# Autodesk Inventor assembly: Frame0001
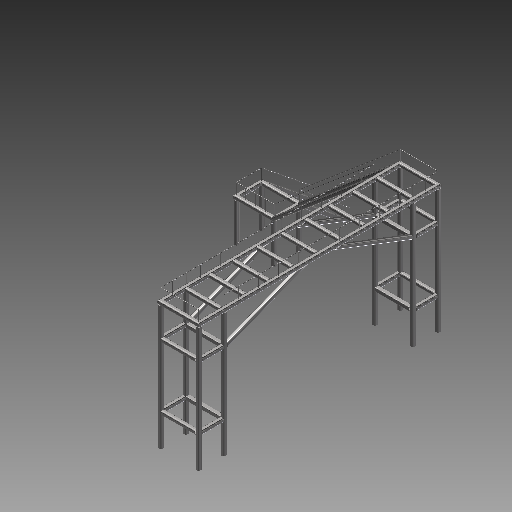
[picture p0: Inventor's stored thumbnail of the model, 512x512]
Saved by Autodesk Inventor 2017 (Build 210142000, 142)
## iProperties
Created: 2017-11
Part Number: Frame0001
Document SubType Name: Assembly
Designer: iusti
Mass: 7.38505e+06 g
Surface Area: 1.18279e+06 cm^2
Volume: 940770 cm^3
Density: 7.85 g/cm^3
_FrameDoc: Frame Assembly
_Version: 15.0.0
Author: iusti
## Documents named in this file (202)
- C:\Users\iusti\Desktop\pasarela\Schelet pasarela\Frame\Frame0001.iam
- C:\Users\iusti\Desktop\pasarela\Schelet pasarela\Frame\Skeleton0001.ipt
- C:\Users\iusti\Desktop\pasarela\Schelet pasarela\Frame\DIN 150 x 150 x 16 00000063.ipt
- DIN 200 x 200 x 16 00000017.ipt
- C:\Users\iusti\Desktop\pasarela\Schelet pasarela\Frame\DIN 150 x 150 x 16 00000064.ipt
- DIN 200 x 200 x 16 00000019.ipt
- C:\Users\iusti\Desktop\pasarela\Schelet pasarela\Frame\DIN 150 x 150 x 16 00000065.ipt
- DIN 200 x 200 x 16 00000018.ipt
- C:\Users\iusti\Desktop\pasarela\Schelet pasarela\Frame\DIN 150 x 150 x 16 00000066.ipt
- DIN 200 x 200 x 16 00000020.ipt
- C:\Users\iusti\Desktop\pasarela\Schelet pasarela\Frame\DIN 150 x 150 x 16 00000067.ipt
- DIN 200 x 200 x 16 00000021.ipt
- C:\Users\iusti\Desktop\pasarela\Schelet pasarela\Frame\DIN 150 x 150 x 16 00000068.ipt
- DIN 200 x 200 x 16 00000022.ipt
- C:\Users\iusti\Desktop\pasarela\Schelet pasarela\Frame\DIN 150 x 150 x 16 00000069.ipt
- DIN 200 x 200 x 16 00000023.ipt
- C:\Users\iusti\Desktop\pasarela\Schelet pasarela\Frame\DIN 150 x 150 x 16 00000070.ipt
- DIN 200 x 200 x 16 00000024.ipt
- C:\Users\iusti\Desktop\pasarela\Schelet pasarela\Frame\DIN 150 x 150 x 16 00000071.ipt
- DIN 200 x 200 x 16 00000025.ipt
- C:\Users\iusti\Desktop\pasarela\Schelet pasarela\Frame\DIN 150 x 150 x 16 00000072.ipt
- DIN 200 x 200 x 16 00000026.ipt
- C:\Users\iusti\Desktop\pasarela\Schelet pasarela\Frame\DIN 150 x 150 x 16 00000073.ipt
- DIN 200 x 200 x 16 00000027.ipt
- C:\Users\iusti\Desktop\pasarela\Schelet pasarela\Frame\DIN 150 x 150 x 16 00000074.ipt
- DIN 200 x 200 x 16 00000028.ipt
- C:\Users\iusti\Desktop\pasarela\Schelet pasarela\Frame\DIN 150 x 150 x 16 00000075.ipt
- DIN 200 x 200 x 16 00000029.ipt
- C:\Users\iusti\Desktop\pasarela\Schelet pasarela\Frame\DIN 150 x 150 x 16 00000076.ipt
- DIN 200 x 200 x 16 00000030.ipt
- C:\Users\iusti\Desktop\pasarela\Schelet pasarela\Frame\DIN 150 x 150 x 16 00000077.ipt
- DIN 200 x 200 x 16 00000031.ipt
- C:\Users\iusti\Desktop\pasarela\Schelet pasarela\Frame\DIN 150 x 150 x 16 00000078.ipt
- DIN 200 x 200 x 16 00000033.ipt
- C:\Users\iusti\Desktop\pasarela\Schelet pasarela\Frame\DIN 150 x 150 x 16 00000079.ipt
- DIN 200 x 200 x 16 00000034.ipt
- C:\Users\iusti\Desktop\pasarela\Schelet pasarela\Frame\DIN 150 x 150 x 16 00000080.ipt
- DIN 200 x 200 x 16 00000035.ipt
- C:\Users\iusti\Desktop\pasarela\Schelet pasarela\Frame\DIN 150 x 150 x 16 00000081.ipt
- DIN 200 x 200 x 16 00000036.ipt
- C:\Users\iusti\Desktop\pasarela\Schelet pasarela\Frame\DIN 150 x 150 x 16 00000082.ipt
- DIN 200 x 200 x 16 00000037.ipt
- C:\Users\iusti\Desktop\pasarela\Schelet pasarela\Frame\DIN 150 x 150 x 16 00000083.ipt
- DIN 200 x 200 x 16 00000038.ipt
- C:\Users\iusti\Desktop\pasarela\Schelet pasarela\Frame\DIN 150 x 150 x 16 00000084.ipt
- DIN 200 x 200 x 16 00000039.ipt
- C:\Users\iusti\Desktop\pasarela\Schelet pasarela\Frame\DIN 150 x 150 x 16 00000085.ipt
- DIN 200 x 200 x 16 00000040.ipt
- C:\Users\iusti\Desktop\pasarela\Schelet pasarela\Frame\DIN 150 x 150 x 16 00000086.ipt
- DIN 200 x 200 x 16 00000041.ipt
- C:\Users\iusti\Desktop\pasarela\Schelet pasarela\Frame\DIN 150 x 150 x 16 00000087.ipt
- DIN 200 x 200 x 16 00000042.ipt
- C:\Users\iusti\Desktop\pasarela\Schelet pasarela\Frame\DIN 150 x 150 x 16 00000088.ipt
- DIN 200 x 200 x 16 00000043.ipt
- C:\Users\iusti\Desktop\pasarela\Schelet pasarela\Frame\DIN 150 x 150 x 16 00000089.ipt
- DIN 200 x 200 x 16 00000044.ipt
- C:\Users\iusti\Desktop\pasarela\Schelet pasarela\Frame\DIN 150 x 150 x 16 00000090.ipt
- DIN 200 x 200 x 16 00000047.ipt
- C:\Users\iusti\Desktop\pasarela\Schelet pasarela\Frame\DIN 150 x 150 x 16 00000091.ipt
- DIN 200 x 200 x 16 00000048.ipt
- C:\Users\iusti\Desktop\pasarela\Schelet pasarela\Frame\DIN 150 x 150 x 16 00000092.ipt
- DIN 200 x 200 x 16 00000049.ipt
- C:\Users\iusti\Desktop\pasarela\Schelet pasarela\Frame\DIN 150 x 150 x 16 00000093.ipt
- DIN 200 x 200 x 16 00000050.ipt
- C:\Users\iusti\Desktop\pasarela\Schelet pasarela\Frame\DIN 150 x 150 x 16 00000094.ipt
- DIN 200 x 200 x 16 00000011.ipt
- C:\Users\iusti\Desktop\pasarela\Schelet pasarela\Frame\DIN 150 x 150 x 16 00000095.ipt
- DIN 200 x 200 x 16 00000013.ipt
- C:\Users\iusti\Desktop\pasarela\Schelet pasarela\Frame\DIN 150 x 150 x 16 00000096.ipt
- DIN 200 x 200 x 16 00000012.ipt
- C:\Users\iusti\Desktop\pasarela\Schelet pasarela\Frame\DIN 150 x 150 x 16 00000097.ipt
- DIN 200 x 200 x 16 00000014.ipt
- C:\Users\iusti\Desktop\pasarela\Schelet pasarela\Frame\DIN 150 x 150 x 16 00000098.ipt
- DIN 200 x 200 x 16 00000015.ipt
- C:\Users\iusti\Desktop\pasarela\Schelet pasarela\Frame\DIN 150 x 150 x 16 00000099.ipt
- DIN 200 x 200 x 16 00000016.ipt
- C:\Users\iusti\Desktop\pasarela\Schelet pasarela\Frame\DIN 150 x 150 x 16 00000100.ipt
- DIN 150 x 150 x 16 00000100.ipt
- C:\Users\iusti\Desktop\pasarela\Schelet pasarela\Frame\DIN 150 x 150 x 16 00000101.ipt
- DIN 150 x 150 x 16 00000101.ipt
- C:\Users\iusti\Desktop\pasarela\Schelet pasarela\Frame\DIN 150 x 150 x 16 00000102.ipt
- DIN 150 x 150 x 16 00000102.ipt
- C:\Users\iusti\Desktop\pasarela\Schelet pasarela\Frame\DIN 150 x 150 x 16 00000103.ipt
- DIN 150 x 150 x 16 00000103.ipt
- C:\Users\iusti\Desktop\pasarela\Schelet pasarela\Frame\DIN 150 x 150 x 16 00000104.ipt
- DIN 150 x 150 x 16 00000104.ipt
- C:\Users\iusti\Desktop\pasarela\Schelet pasarela\Frame\DIN 150 x 150 x 16 00000105.ipt
- DIN 150 x 150 x 16 00000105.ipt
- C:\Users\iusti\Desktop\pasarela\Schelet pasarela\Frame\DIN 150 x 150 x 16 00000106.ipt
- DIN 150 x 150 x 16 00000106.ipt
- C:\Users\iusti\Desktop\pasarela\Schelet pasarela\Frame\DIN 150 x 150 x 16 00000107.ipt
- DIN 150 x 150 x 16 00000107.ipt
- C:\Users\iusti\Desktop\pasarela\Schelet pasarela\Frame\DIN 150 x 150 x 16 00000108.ipt
- DIN 150 x 150 x 16 00000108.ipt
- C:\Users\iusti\Desktop\pasarela\Schelet pasarela\Frame\DIN 150 x 150 x 16 00000109.ipt
- DIN 150 x 150 x 16 00000109.ipt
- C:\Users\iusti\Desktop\pasarela\Schelet pasarela\Frame\DIN 150 x 150 x 16 00000110.ipt
- DIN 150 x 150 x 16 00000110.ipt
- C:\Users\iusti\Desktop\pasarela\Schelet pasarela\Frame\DIN 150 x 150 x 16 00000111.ipt
- DIN 150 x 150 x 16 00000111.ipt
- C:\Users\iusti\Desktop\pasarela\Schelet pasarela\Frame\DIN 150 x 150 x 16 00000112.ipt
- DIN 150 x 150 x 16 00000112.ipt
- C:\Users\iusti\Desktop\pasarela\Schelet pasarela\Frame\DIN 150 x 150 x 16 00000113.ipt
- DIN 150 x 150 x 16 00000113.ipt
- C:\Users\iusti\Desktop\pasarela\Schelet pasarela\Frame\DIN 150 x 150 x 16 00000116.ipt
- DIN 150 x 150 x 16 00000116.ipt
- C:\Users\iusti\Desktop\pasarela\Schelet pasarela\Frame\DIN 150 x 150 x 16 00000117.ipt
- DIN 150 x 150 x 16 00000117.ipt
- C:\Users\iusti\Desktop\pasarela\Schelet pasarela\Frame\DIN 21.3 x 2.3 00000118.ipt
- DIN 21.3 x 2.3 00000118.ipt
- C:\Users\iusti\Desktop\pasarela\Schelet pasarela\Frame\DIN 21.3 x 2.3 00000119.ipt
- DIN 21.3 x 2.3 00000119.ipt
- C:\Users\iusti\Desktop\pasarela\Schelet pasarela\Frame\DIN 21.3 x 2.3 00000120.ipt
- DIN 21.3 x 2.3 00000120.ipt
- C:\Users\iusti\Desktop\pasarela\Schelet pasarela\Frame\DIN 21.3 x 2.3 00000121.ipt
- DIN 21.3 x 2.3 00000121.ipt
- C:\Users\iusti\Desktop\pasarela\Schelet pasarela\Frame\DIN 21.3 x 2.3 00000122.ipt
- DIN 21.3 x 2.3 00000122.ipt
- C:\Users\iusti\Desktop\pasarela\Schelet pasarela\Frame\DIN 21.3 x 2.3 00000123.ipt
- DIN 21.3 x 2.3 00000123.ipt
- C:\Users\iusti\Desktop\pasarela\Schelet pasarela\Frame\DIN 21.3 x 2.3 00000124.ipt
- DIN 21.3 x 2.3 00000124.ipt
- C:\Users\iusti\Desktop\pasarela\Schelet pasarela\Frame\DIN 21.3 x 2.3 00000125.ipt
- DIN 21.3 x 2.3 00000125.ipt
- C:\Users\iusti\Desktop\pasarela\Schelet pasarela\Frame\DIN 21.3 x 2.3 00000126.ipt
- DIN 21.3 x 2.3 00000126.ipt
- C:\Users\iusti\Desktop\pasarela\Schelet pasarela\Frame\DIN 21.3 x 2.3 00000127.ipt
- DIN 21.3 x 2.3 00000127.ipt
- C:\Users\iusti\Desktop\pasarela\Schelet pasarela\Frame\DIN 21.3 x 2.3 00000128.ipt
- DIN 21.3 x 2.3 00000128.ipt
- C:\Users\iusti\Desktop\pasarela\Schelet pasarela\Frame\DIN 21.3 x 2.3 00000129.ipt
- DIN 21.3 x 2.3 00000129.ipt
- C:\Users\iusti\Desktop\pasarela\Schelet pasarela\Frame\DIN 21.3 x 2.3 00000130.ipt
- DIN 21.3 x 2.3 00000130.ipt
- C:\Users\iusti\Desktop\pasarela\Schelet pasarela\Frame\DIN 21.3 x 2.3 00000131.ipt
- DIN 21.3 x 2.3 00000131.ipt
- C:\Users\iusti\Desktop\pasarela\Schelet pasarela\Frame\DIN 21.3 x 2.3 00000132.ipt
- DIN 21.3 x 2.3 00000132.ipt
- C:\Users\iusti\Desktop\pasarela\Schelet pasarela\Frame\DIN 21.3 x 2.3 00000133.ipt
- DIN 21.3 x 2.3 00000133.ipt
- C:\Users\iusti\Desktop\pasarela\Schelet pasarela\Frame\DIN 21.3 x 2.3 00000134.ipt
- DIN 21.3 x 2.3 00000134.ipt
- C:\Users\iusti\Desktop\pasarela\Schelet pasarela\Frame\DIN 21.3 x 2.3 00000135.ipt
- DIN 21.3 x 2.3 00000135.ipt
- C:\Users\iusti\Desktop\pasarela\Schelet pasarela\Frame\DIN 21.3 x 2.3 00000136.ipt
- DIN 21.3 x 2.3 00000136.ipt
- C:\Users\iusti\Desktop\pasarela\Schelet pasarela\Frame\DIN 21.3 x 2.3 00000137.ipt
- DIN 21.3 x 2.3 00000137.ipt
- C:\Users\iusti\Desktop\pasarela\Schelet pasarela\Frame\DIN 21.3 x 2.3 00000138.ipt
- DIN 21.3 x 2.3 00000138.ipt
- C:\Users\iusti\Desktop\pasarela\Schelet pasarela\Frame\DIN 21.3 x 2.3 00000139.ipt
- DIN 21.3 x 2.3 00000139.ipt
- C:\Users\iusti\Desktop\pasarela\Schelet pasarela\Frame\DIN 21.3 x 2.3 00000140.ipt
- DIN 21.3 x 2.3 00000140.ipt
- C:\Users\iusti\Desktop\pasarela\Schelet pasarela\Frame\DIN 21.3 x 2.3 00000141.ipt
- DIN 21.3 x 2.3 00000141.ipt
- C:\Users\iusti\Desktop\pasarela\Schelet pasarela\Frame\DIN 21.3 x 2.3 00000142.ipt
- DIN 21.3 x 2.3 00000142.ipt
- C:\Users\iusti\Desktop\pasarela\Schelet pasarela\Frame\DIN 21.3 x 2.3 00000143.ipt
- DIN 21.3 x 2.3 00000143.ipt
- C:\Users\iusti\Desktop\pasarela\Schelet pasarela\Frame\DIN 21.3 x 2.3 00000144.ipt
- DIN 21.3 x 2.3 00000144.ipt
- C:\Users\iusti\Desktop\pasarela\Schelet pasarela\Frame\DIN 21.3 x 2.3 00000145.ipt
- DIN 21.3 x 2.3 00000145.ipt
- C:\Users\iusti\Desktop\pasarela\Schelet pasarela\Frame\DIN 21.3 x 2.3 00000146.ipt
- DIN 21.3 x 2.3 00000146.ipt
- C:\Users\iusti\Desktop\pasarela\Schelet pasarela\Frame\DIN 21.3 x 2.3 00000147.ipt
- DIN 21.3 x 2.3 00000147.ipt
- C:\Users\iusti\Desktop\pasarela\Schelet pasarela\Frame\DIN 21.3 x 2.3 00000148.ipt
- DIN 21.3 x 2.3 00000148.ipt
- C:\Users\iusti\Desktop\pasarela\Schelet pasarela\Frame\DIN 21.3 x 2.3 00000149.ipt
- DIN 21.3 x 2.3 00000149.ipt
- C:\Users\iusti\Desktop\pasarela\Schelet pasarela\Frame\DIN 21.3 x 2.3 00000150.ipt
- DIN 21.3 x 2.3 00000150.ipt
- C:\Users\iusti\Desktop\pasarela\Schelet pasarela\Frame\DIN 21.3 x 2.3 00000151.ipt
- DIN 21.3 x 2.3 00000151.ipt
- C:\Users\iusti\Desktop\pasarela\Schelet pasarela\Frame\DIN 21.3 x 2.3 00000152.ipt
- DIN 21.3 x 2.3 00000152.ipt
- C:\Users\iusti\Desktop\pasarela\Schelet pasarela\Frame\DIN 21.3 x 2.3 00000153.ipt
- DIN 21.3 x 2.3 00000153.ipt
- C:\Users\iusti\Desktop\pasarela\Schelet pasarela\Frame\DIN 21.3 x 2.3 00000154.ipt
- DIN 21.3 x 2.3 00000154.ipt
- C:\Users\iusti\Desktop\pasarela\Schelet pasarela\Frame\DIN 21.3 x 2.3 00000155.ipt
- DIN 21.3 x 2.3 00000155.ipt
- C:\Users\iusti\Desktop\pasarela\Schelet pasarela\Frame\DIN 21.3 x 2.3 00000156.ipt
- DIN 21.3 x 2.3 00000156.ipt
- C:\Users\iusti\Desktop\pasarela\Schelet pasarela\Frame\DIN 21.3 x 2.3 00000157.ipt
- DIN 21.3 x 2.3 00000157.ipt
- C:\Users\iusti\Desktop\pasarela\Schelet pasarela\Frame\DIN 21.3 x 2.3 00000158.ipt
- DIN 21.3 x 2.3 00000158.ipt
- C:\Users\iusti\Desktop\pasarela\Schelet pasarela\Frame\DIN 21.3 x 2.3 00000159.ipt
- DIN 21.3 x 2.3 00000159.ipt
- C:\Users\iusti\Desktop\pasarela\Schelet pasarela\Frame\DIN 21.3 x 2.3 00000160.ipt
- DIN 21.3 x 2.3 00000160.ipt
- C:\Users\iusti\Desktop\pasarela\Schelet pasarela\Frame\DIN 21.3 x 2.3 00000161.ipt
- DIN 21.3 x 2.3 00000161.ipt
- C:\Users\iusti\Desktop\pasarela\Schelet pasarela\Frame\DIN 21.3 x 2.3 00000162.ipt
- DIN 21.3 x 2.3 00000162.ipt
- C:\Users\iusti\Desktop\pasarela\Schelet pasarela\Frame\DIN 21.3 x 2.3 00000163.ipt
- DIN 21.3 x 2.3 00000163.ipt
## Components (101 placed, 101 different names)
1. Frame Reference Model
2. DIN 150 x 150 x 16 00000094:1
3. DIN 150 x 150 x 16 00000095:1
4. DIN 150 x 150 x 16 00000096:1
5. DIN 150 x 150 x 16 00000097:1
6. DIN 150 x 150 x 16 00000098:1
7. DIN 150 x 150 x 16 00000099:1
8. DIN 150 x 150 x 16 00000063:1
9. DIN 150 x 150 x 16 00000064:1
10. DIN 150 x 150 x 16 00000065:1
11. DIN 150 x 150 x 16 00000066:1
12. DIN 150 x 150 x 16 00000067:1
13. DIN 150 x 150 x 16 00000068:1
14. DIN 150 x 150 x 16 00000069:1
15. DIN 150 x 150 x 16 00000070:1
16. DIN 150 x 150 x 16 00000071:1
17. DIN 150 x 150 x 16 00000072:1
18. DIN 150 x 150 x 16 00000073:1
19. DIN 150 x 150 x 16 00000074:1
20. DIN 150 x 150 x 16 00000075:1
21. DIN 150 x 150 x 16 00000076:1
22. DIN 150 x 150 x 16 00000077:1
23. DIN 150 x 150 x 16 00000078:1
24. DIN 150 x 150 x 16 00000079:1
25. DIN 150 x 150 x 16 00000080:1
26. DIN 150 x 150 x 16 00000081:1
27. DIN 150 x 150 x 16 00000082:1
28. DIN 150 x 150 x 16 00000083:1
29. DIN 150 x 150 x 16 00000084:1
30. DIN 150 x 150 x 16 00000085:1
31. DIN 150 x 150 x 16 00000086:1
32. DIN 150 x 150 x 16 00000087:1
33. DIN 150 x 150 x 16 00000088:1
34. DIN 150 x 150 x 16 00000089:1
35. DIN 150 x 150 x 16 00000090:1
36. DIN 150 x 150 x 16 00000091:1
37. DIN 150 x 150 x 16 00000092:1
38. DIN 150 x 150 x 16 00000093:1
39. DIN 150 x 150 x 16 00000100:1
40. DIN 150 x 150 x 16 00000101:1
41. DIN 150 x 150 x 16 00000102:1
42. DIN 150 x 150 x 16 00000103:1
43. DIN 150 x 150 x 16 00000104:1
44. DIN 150 x 150 x 16 00000105:1
45. DIN 150 x 150 x 16 00000106:1
46. DIN 150 x 150 x 16 00000107:1
47. DIN 150 x 150 x 16 00000108:1
48. DIN 150 x 150 x 16 00000109:1
49. DIN 150 x 150 x 16 00000110:1
50. DIN 150 x 150 x 16 00000111:1
51. DIN 150 x 150 x 16 00000112:1
52. DIN 150 x 150 x 16 00000113:1
53. DIN 150 x 150 x 16 00000116:1
54. DIN 150 x 150 x 16 00000117:1
55. DIN 21.3 x 2.3 00000118:1
56. DIN 21.3 x 2.3 00000119:1
57. DIN 21.3 x 2.3 00000120:1
58. DIN 21.3 x 2.3 00000121:1
59. DIN 21.3 x 2.3 00000122:1
60. DIN 21.3 x 2.3 00000123:1
61. DIN 21.3 x 2.3 00000124:1
62. DIN 21.3 x 2.3 00000125:1
63. DIN 21.3 x 2.3 00000126:1
64. DIN 21.3 x 2.3 00000127:1
65. DIN 21.3 x 2.3 00000128:1
66. DIN 21.3 x 2.3 00000129:1
67. DIN 21.3 x 2.3 00000130:1
68. DIN 21.3 x 2.3 00000131:1
69. DIN 21.3 x 2.3 00000132:1
70. DIN 21.3 x 2.3 00000133:1
71. DIN 21.3 x 2.3 00000134:1
72. DIN 21.3 x 2.3 00000135:1
73. DIN 21.3 x 2.3 00000136:1
74. DIN 21.3 x 2.3 00000137:1
75. DIN 21.3 x 2.3 00000138:1
76. DIN 21.3 x 2.3 00000139:1
77. DIN 21.3 x 2.3 00000140:1
78. DIN 21.3 x 2.3 00000141:1
79. DIN 21.3 x 2.3 00000142:1
80. DIN 21.3 x 2.3 00000143:1
81. DIN 21.3 x 2.3 00000144:1
82. DIN 21.3 x 2.3 00000145:1
83. DIN 21.3 x 2.3 00000146:1
84. DIN 21.3 x 2.3 00000147:1
85. DIN 21.3 x 2.3 00000148:1
86. DIN 21.3 x 2.3 00000149:1
87. DIN 21.3 x 2.3 00000150:1
88. DIN 21.3 x 2.3 00000151:1
89. DIN 21.3 x 2.3 00000152:1
90. DIN 21.3 x 2.3 00000153:1
91. DIN 21.3 x 2.3 00000154:1
92. DIN 21.3 x 2.3 00000155:1
93. DIN 21.3 x 2.3 00000156:1
94. DIN 21.3 x 2.3 00000157:1
95. DIN 21.3 x 2.3 00000158:1
96. DIN 21.3 x 2.3 00000159:1
97. DIN 21.3 x 2.3 00000160:1
98. DIN 21.3 x 2.3 00000161:1
99. DIN 21.3 x 2.3 00000162:1
100. DIN 21.3 x 2.3 00000163:1
101. DIN 21.3 x 2.3 00000164:1
